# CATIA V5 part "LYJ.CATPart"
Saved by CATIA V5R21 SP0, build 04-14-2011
Part number: LYJ.SLDPRT
Bounding box of the stored display mesh (mm): x -1.362 to 1.338, y -0.976 to 1.024, z 2.1 to 2.7
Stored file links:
  C:\Users\user\Desktop\CATIA文件\0-最新文件\LYJ\LYJ.CATPart
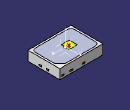
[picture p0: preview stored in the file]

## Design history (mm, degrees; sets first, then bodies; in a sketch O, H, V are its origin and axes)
AxisSystem1: origin (-0.0115, 0.0244, 2.7), X (1, 0, 0), Y (0, 1, 0), Z (0, 0, 1)
Set1
  DatumSurface1 to DatumSurface42
  Line1: stored without definition
  Circle1: stored without definition
  Line2: stored without definition
  Circle2: stored without definition
  Line3: stored without definition
  Circle3: stored without definition
  Line4: stored without definition
  Circle4: stored without definition
  Line5: stored without definition
  Circle5: stored without definition
  Line6: stored without definition
  Circle6: stored without definition
  Line7: stored without definition
  Circle7: stored without definition
  Line8: stored without definition
  Line9: stored without definition
  Circle8: stored without definition
  Line10: stored without definition
  Line11: stored without definition
  Circle9: stored without definition
  Line12: stored without definition
  Line13: stored without definition
  Circle10: stored without definition
  Line14 to Line18: stored without definition
  Circle11: stored without definition
  Line19: stored without definition
  Circle12: stored without definition
  Line20: stored without definition
  Circle13: stored without definition
  Line21: stored without definition
  Circle14: stored without definition
  Line22: stored without definition
  Circle15: stored without definition
  Line23: stored without definition
  Circle16: stored without definition
  Line24: stored without definition
  Circle17: stored without definition
  Line25: stored without definition
  Circle18: stored without definition
  Line26: stored without definition
  Circle19: stored without definition
  Line27: stored without definition
  Circle20: stored without definition
  Line28 to Line30: stored without definition
  Circle21: stored without definition
  Line31: stored without definition
  Circle22: stored without definition
  Line32: stored without definition
  Circle23: stored without definition
  Line33: stored without definition
  Circle24: stored without definition
  Line34: stored without definition
  Line35: stored without definition
  Circle25: stored without definition
  Line36: stored without definition
  Circle26: stored without definition
  Line37: stored without definition
  Circle27: stored without definition
  Line38: stored without definition
  Circle28: stored without definition
  Line39: stored without definition
  Circle29: stored without definition
  Line40: stored without definition
  Circle30: stored without definition
  Line41: stored without definition
  Circle31: stored without definition
  Line42: stored without definition
  Circle32: stored without definition
  Line43: stored without definition
  Circle33: stored without definition
  Line44 to Line46: stored without definition
  Circle34: stored without definition
  Line47: stored without definition
  Circle35: stored without definition
  Line48: stored without definition
  Circle36: stored without definition
  Line49: stored without definition
  Circle37: stored without definition
  Line50: stored without definition
  Circle38: stored without definition
  Line51 to Line79: stored without definition
  DatumSurface43 to DatumSurface79
  Line80: stored without definition
  Circle39: stored without definition
  Line81: stored without definition
  Circle40: stored without definition
  Line82: stored without definition
  Circle41: stored without definition
  Line83: stored without definition
  Circle42: stored without definition
  Circle43: stored without definition
  Line84 to Line87: stored without definition
  Circle44: stored without definition
  Line88 to Line90: stored without definition
  Circle45: stored without definition
  Line91 to Line93: stored without definition
  Circle46: stored without definition
  Line94: stored without definition
  Line95: stored without definition
  Circle47: stored without definition
  Line96: stored without definition
  Circle48: stored without definition
  Line97: stored without definition
  Circle49: stored without definition
  Line98 to Line100: stored without definition
  Circle50: stored without definition
  Line101: stored without definition
  Circle51: stored without definition
  Line102: stored without definition
  Circle52: stored without definition
  Line103: stored without definition
  Circle53: stored without definition
  Line104: stored without definition
  Circle54: stored without definition
  Line105 to Line107: stored without definition
  Circle55: stored without definition
  Line108: stored without definition
  Circle56: stored without definition
  Line109 to Line112: stored without definition
  Circle57: stored without definition
  Line113: stored without definition
  Circle58: stored without definition
  Line114: stored without definition
  Circle59: stored without definition
  Line115 to Line117: stored without definition
  Circle60: stored without definition
  Line118: stored without definition
  Circle61: stored without definition
  Line119: stored without definition
  Circle62: stored without definition
  Line120: stored without definition
  Circle63: stored without definition
  Line121: stored without definition
  Circle64: stored without definition
  Line122 to Line124: stored without definition
  Circle65: stored without definition
  Line125: stored without definition
  Circle66: stored without definition
  Line126 to Line153: stored without definition
  DatumSurface80 to DatumSurface154
  DatumCurve1
  DatumCurve2
  Circle67: stored without definition
  Line154: stored without definition
  Circle68: stored without definition
  Line155: stored without definition
  Line156: stored without definition
  Circle69: stored without definition
  Line157: stored without definition
  Circle70: stored without definition
  Line158 to Line160: stored without definition
  Circle71: stored without definition
  Line161: stored without definition
  Circle72: stored without definition
  Line162 to Line164: stored without definition
  Circle73: stored without definition
  Line165: stored without definition
  Circle74: stored without definition
  Line166 to Line168: stored without definition
  Circle75: stored without definition
  Line169: stored without definition
  Circle76: stored without definition
  Line170: stored without definition
  Line171: stored without definition
  Circle77: stored without definition
  Line172: stored without definition
  Circle78: stored without definition
  Line173: stored without definition
  Circle79: stored without definition
  Line174 to Line176: stored without definition
  Circle80: stored without definition
  Line177: stored without definition
  Circle81: stored without definition
  Line178: stored without definition
  Circle82: stored without definition
  Line179: stored without definition
  Circle83: stored without definition
  Line180: stored without definition
  Circle84: stored without definition
  Line181 to Line183: stored without definition
  Circle85: stored without definition
  Line184: stored without definition
  Circle86: stored without definition
  Line185 to Line187: stored without definition
  Circle87: stored without definition
  Line188: stored without definition
  Line189: stored without definition
  Circle88: stored without definition
  Line190: stored without definition
  Line191: stored without definition
  Circle89: stored without definition
  Line192 to Line198: stored without definition
  Circle90: stored without definition
  Line199 to Line202: stored without definition
  Circle91: stored without definition
  Line203: stored without definition
  Line204: stored without definition
  Circle92: stored without definition
  Line205 to Line208: stored without definition
  Circle93: stored without definition
  Line209: stored without definition
  Line210: stored without definition
  Circle94: stored without definition
  Line211 to Line216: stored without definition
  Circle95: stored without definition
  Line217 to Line219: stored without definition
  Circle96: stored without definition
  Line220 to Line229: stored without definition
  Circle97: stored without definition
  Line230: stored without definition
  Circle98: stored without definition
  Line231: stored without definition
  Circle99: stored without definition
  Line232: stored without definition
  Circle100: stored without definition
  Line233: stored without definition
  Circle101: stored without definition
  Line234: stored without definition
  Circle102: stored without definition
  Line235: stored without definition
  Circle103: stored without definition
  Line236: stored without definition
  Circle104: stored without definition
  Line237 to Line245: stored without definition
  Circle105: stored without definition
  Line246: stored without definition
  Circle106: stored without definition
  Line247: stored without definition
  Circle107: stored without definition
  Line248: stored without definition
  Circle108: stored without definition
  Line249: stored without definition
  Circle109: stored without definition
  Line250: stored without definition
  Circle110: stored without definition
  Line251: stored without definition
  Circle111: stored without definition
  Line252: stored without definition
  Circle112: stored without definition
  Line253: stored without definition
  Circle113: stored without definition
  Line254: stored without definition
  Circle114: stored without definition
  Line255: stored without definition
  Circle115: stored without definition
  Line256: stored without definition
  Circle116: stored without definition
  Line257: stored without definition
  Circle117: stored without definition
  Line258 to Line260: stored without definition
  Circle118: stored without definition
  Line261: stored without definition
  Circle119: stored without definition
  Line262: stored without definition
  Circle120: stored without definition
  Line263: stored without definition
  Circle121: stored without definition
  Line264: stored without definition
  Circle122: stored without definition
  Line265: stored without definition
  Circle123: stored without definition
  Line266: stored without definition
  Circle124: stored without definition
  Line267: stored without definition
  Circle125: stored without definition
  Line268: stored without definition
  Circle126: stored without definition
  Line269: stored without definition
  Circle127: stored without definition
  Line270: stored without definition
  Circle128: stored without definition
  Line271 to Line273: stored without definition
  Circle129: stored without definition
  Line274: stored without definition
  Circle130: stored without definition
  Line275: stored without definition
  Circle131: stored without definition
  Line276: stored without definition
  Circle132: stored without definition
  Line277 to Line313: stored without definition
  DatumCurve3
  Line314: stored without definition
  DatumCurve4
  Line315: stored without definition
  DatumCurve5
  Line316: stored without definition
  DatumCurve6
  Line317: stored without definition
  DatumCurve7
  Line318 to Line323: stored without definition
  DatumCurve8
  Line324: stored without definition
  DatumCurve9
  Line325: stored without definition
  DatumCurve10
  Line326: stored without definition
  DatumCurve11
  Line327: stored without definition
  DatumCurve12
  Line328 to Line336: stored without definition
  Point1 "几何中心（测试原点）": type Between, FirstPoint vertex [face of DatumSurface148], SecondPoint vertex [face of DatumSurface147], Ratio 0.5
  Point2 "发光中心": type Between, FirstPoint vertex [face of DatumSurface154], SecondPoint vertex [face of DatumSurface154], Ratio 0.5
  Point3 "虚拟坐标": (-0.236, -0.009, -0.1), relative to Point1, in AxisSystem1
Body1 (main body)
